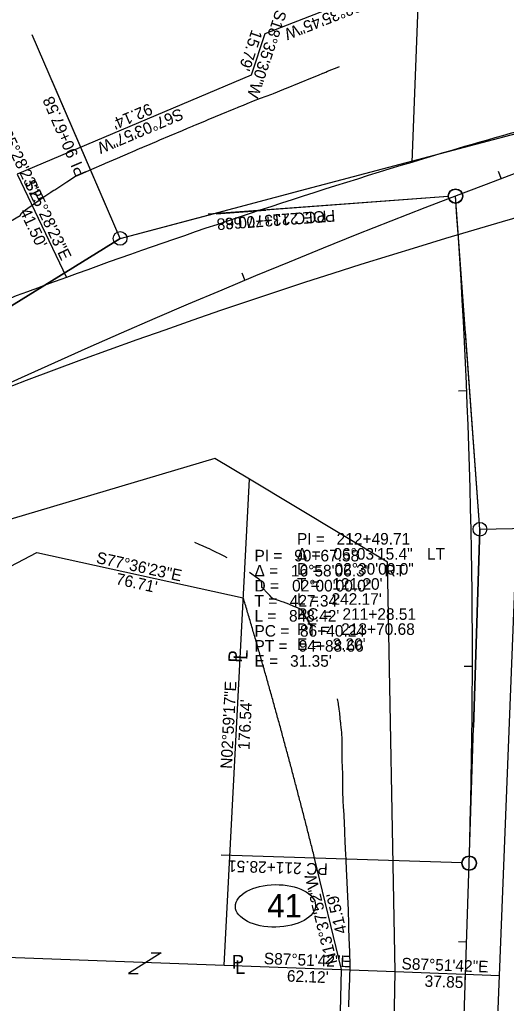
# Model space of a CAD drawing. Extents: x 1145508 to 2262867, y -3126236 to 2021677.
# Drawn here: x 1151538.5 to 1151715.1, y 2020154.7 to 2020511.6 of the extents above; entities that cross this region are included whole.
import ezdxf

# ---------------------------------------------------------------- set-up
doc = ezdxf.new("R2010")
doc.units = 0
for name, color, linetype in [('Default', 7, 'Continuous'), ('DSN_DRFT_Guideline-No-Plot', 7, 'Continuous'), ('DSN_RDWY_Alignment', 7, 'Continuous'), ('DSN_RDWY_Alignment Annotation', 7, 'Continuous'), ('DSN_RDWY_Const Limits', 7, 'Continuous'), ('DSN_ROW_Annotation', 7, 'Continuous'), ('DSN_ROW_Esmnt', 7, 'Continuous'), ('DSN_ROW_Line', 7, 'Continuous'), ('DSN_ROW_Line-Annotation', 7, 'Continuous'), ('DSN_ROW_Prop-Line', 7, 'Continuous'), ('DSN_ROW_Prop-Line-Annotation', 7, 'Continuous'), ('E_Const Align', 7, 'Continuous'), ('EX_QSECTION', 7, 'Continuous'), ('EX_ROW', 7, 'Continuous'), ('EX_ROW_ANNOT', 7, 'Continuous'), ('EX_SECTION', 7, 'Continuous')]:
    doc.layers.add(name, color=color, linetype=linetype)

msp = doc.modelspace()

# ---------------------------------------------------------------- linework, layer by layer
at = {"layer": 'Default'}
msp.add_arc((1152351.97, 2018237.09), 2291.83, 105.0994, 122.23857, dxfattribs=at)
msp.add_open_spline([(1151645.52, 2020207.35), (1151645.13, 2020208.94), (1151644.33, 2020212.12), (1151643.12, 2020216.89), (1151641.91, 2020221.65), (1151640.68, 2020226.41), (1151639.44, 2020231.16), (1151638.2, 2020235.91), (1151636.94, 2020240.65), (1151635.67, 2020245.39), (1151634.39, 2020250.12), (1151633.11, 2020254.84), (1151631.81, 2020259.56), (1151630.5, 2020264.28), (1151629.19, 2020268.99), (1151627.86, 2020273.69), (1151626.52, 2020278.38), (1151625.17, 2020283.08), (1151623.82, 2020287.76), (1151622.45, 2020292.44), (1151621.07, 2020297.11), (1151620.15, 2020300.23), (1151619.68, 2020301.78)], degree=3, dxfattribs=at)
at = {"layer": 'DSN_DRFT_Guideline-No-Plot'}
msp.add_line((1151683.89, 2020538.97), (1151680.79, 2020459.79), dxfattribs=at)
at = {"layer": 'DSN_RDWY_Alignment'}
for p, q in [((1151636.3, 2020448.46), (1151988, 2020541.79)), ((1151705.52, 2020326.67), (1151696.64, 2020447.54)), ((1151574.96, 2020432.19), (1151612.83, 2020442.24)), ((1151211.88, 2020206.81), (1151574.96, 2020432.19)), ((1151701.6, 2020205.53), (1151705.52, 2020326.67))]:
    msp.add_line(p, q, dxfattribs=at)
for points in [[(1151574.96, 2020432.19), (1151543.07, 2020506.09)], [(1151574.96, 2020432.19), (1151550.19, 2020489.57)]]:
    msp.add_lwpolyline(points, dxfattribs=at)
for centre in [(1151696.64, 2020447.54), (1151574.96, 2020432.19), (1151705.52, 2020326.67), (1151701.6, 2020205.53)]:
    msp.add_circle(centre, 2.5, dxfattribs=at)
at = {"layer": 'DSN_RDWY_Alignment Annotation'}
for p, q in [((1151574.96, 2020432.19), (1151551.18, 2020487.28)), ((1151551.18, 2020487.28), (1151551.18, 2020487.28)), ((1151712.14, 2020456.64), (1151713.2, 2020453.84)), ((1151574.96, 2020432.19), (1151644.55, 2020450.65)), ((1151693.97, 2020447.35), (1151606.88, 2020440.95)), ((1151693.97, 2020447.35), (1151609.87, 2020441.17)), ((1151696.64, 2020447.54), (1151696.64, 2020447.54)), ((1151606.88, 2020440.95), (1151606.88, 2020440.95)), ((1151609.87, 2020441.17), (1151627.82, 2020442.49)), ((1151574.96, 2020432.19), (1151513.79, 2020394.22)), ((1151619.09, 2020419.74), (1151620.25, 2020416.97)), ((1151705.52, 2020326.67), (1151700.24, 2020398.47)), ((1151697.73, 2020376.85), (1151700.73, 2020376.98)), ((1151705.52, 2020326.67), (1151703.19, 2020254.71)), ((1151705.52, 2020326.67), (1151765.5, 2020327.9)), ((1151699.79, 2020277.01), (1151702.79, 2020277.01)), ((1151698.93, 2020205.62), (1151611.64, 2020208.44)), ((1151611.64, 2020208.44), (1151611.64, 2020208.44)), ((1151701.6, 2020205.53), (1151701.6, 2020205.53)), ((1151697.68, 2020177.14), (1151700.68, 2020177.04))]:
    msp.add_line(p, q, dxfattribs=at)
for centre in [(1151696.64, 2020447.54), (1151701.6, 2020205.53)]:
    msp.add_circle(centre, 2.67, dxfattribs=at)
at = {"layer": 'DSN_RDWY_Const Limits'}
for points in [[(1151535.19, 2020438.49), (1151538.68, 2020440.53), (1151539.19, 2020441.33), (1151540.69, 2020442.53), (1151541.56, 2020443.13), (1151542.72, 2020443.99), (1151542.8, 2020444.04), (1151542.96, 2020444.17), (1151543.54, 2020444.59), (1151545.56, 2020446.08), (1151546.93, 2020447.09), (1151549.83, 2020448.95), (1151550.37, 2020449.29), (1151550.93, 2020449.65), (1151551.28, 2020449.87), (1151555.59, 2020452.73), (1151559.13, 2020455.04), (1151560.01, 2020455.37), (1151562.1, 2020456.2), (1151562.5, 2020456.37), (1151562.82, 2020456.51), (1151564.72, 2020457.33), (1151569.24, 2020459.27), (1151569.41, 2020459.34), (1151569.63, 2020459.44), (1151574.09, 2020461.37), (1151578.78, 2020463.39), (1151579.3, 2020463.61), (1151582.26, 2020464.88), (1151582.56, 2020465.01), (1151582.69, 2020465.07), (1151583.47, 2020465.4), (1151584.44, 2020465.81), (1151588.16, 2020467.4), (1151589.38, 2020467.92), (1151592.86, 2020469.39), (1151597.56, 2020471.38), (1151599.48, 2020472.19), (1151601.2, 2020472.91), (1151601.5, 2020473.03), (1151601.71, 2020473.12), (1151602.27, 2020473.36), (1151605.69, 2020474.79), (1151606.97, 2020475.33), (1151609.59, 2020476.41), (1151611.69, 2020477.29), (1151616.4, 2020479.24), (1151617.62, 2020479.74), (1151617.86, 2020479.84), (1151618.03, 2020479.91), (1151619.72, 2020480.6), (1151621.12, 2020481.18), (1151623.41, 2020482.12), (1151625.88, 2020483.03), (1151629.96, 2020484.5), (1151630.67, 2020484.79), (1151634.37, 2020486.32), (1151634.64, 2020486.43), (1151635.39, 2020486.74), (1151640.1, 2020488.68), (1151640.1, 2020488.68), (1151644.83, 2020490.62), (1151646.89, 2020491.46), (1151648.58, 2020492.15), (1151648.68, 2020492.19), (1151649.55, 2020492.55), (1151650.24, 2020492.83), (1151654.28, 2020494.47), (1151654.6, 2020494.6)], [(1151613.86, 2020316.3), (1151612.75, 2020316.87), (1151611.24, 2020317.63), (1151609.72, 2020318.36), (1151608.21, 2020319.11), (1151607.36, 2020319.53), (1151606.7, 2020319.84), (1151606.46, 2020319.95), (1151605.15, 2020320.51), (1151603.62, 2020321.19), (1151602.07, 2020321.84)], [(1151644.29, 2020291.58), (1151644.06, 2020291.99), (1151643.14, 2020293.54), (1151643.1, 2020293.61), (1151642.63, 2020294.37), (1151642.19, 2020295.06), (1151641.21, 2020296.57), (1151640.49, 2020297.64), (1151639.95, 2020297.88), (1151639.79, 2020297.95), (1151639.34, 2020298.15), (1151638.05, 2020298.69), (1151636.15, 2020299.46), (1151634.26, 2020300.18), (1151633.77, 2020300.36), (1151632.39, 2020300.85), (1151630.52, 2020301.48), (1151630.12, 2020301.61), (1151629.25, 2020302.59), (1151628.56, 2020303.33), (1151628.51, 2020303.39), (1151628.51, 2020303.39), (1151628.11, 2020303.82), (1151626.94, 2020305.03), (1151626.45, 2020305.53), (1151626.41, 2020306.9), (1151626.3, 2020307.73), (1151625.48, 2020308.4), (1151625.27, 2020308.57), (1151624.11, 2020309.43), (1151622.72, 2020310.42), (1151621.87, 2020311.01)], [(1151658.01, 2020153.41), (1151658.13, 2020158.4), (1151658.13, 2020158.4), (1151658.27, 2020163.4), (1151658.38, 2020168.4), (1151658.27, 2020173.41), (1151658.04, 2020178.42), (1151657.98, 2020181.93), (1151657.97, 2020182.82), (1151657.96, 2020183.42), (1151657.87, 2020188.43), (1151657.61, 2020193.44), (1151657.29, 2020198.45), (1151657.08, 2020203.46), (1151656.96, 2020206.48), (1151656.94, 2020206.98), (1151656.93, 2020207.27), (1151656.88, 2020208.44), (1151656.68, 2020213.35), (1151656.56, 2020216.49), (1151656.48, 2020218.26), (1151656.44, 2020219.07), (1151656.41, 2020219.72), (1151656.22, 2020223.17), (1151656.07, 2020226), (1151655.95, 2020228.08), (1151655.82, 2020231.63), (1151655.81, 2020232.18), (1151655.81, 2020232.98), (1151655.8, 2020235.5), (1151655.77, 2020237.88), (1151655.51, 2020242.78), (1151655.54, 2020244.18), (1151655.54, 2020244.61), (1151655.55, 2020244.94), (1151655.55, 2020244.99), (1151655.58, 2020247.42), (1151655.58, 2020247.43), (1151655.58, 2020247.43), (1151655.59, 2020247.66), (1151655.58, 2020249.22), (1151655.51, 2020251.01), (1151655.43, 2020252.25), (1151655.39, 2020252.79), (1151655.28, 2020254.03), (1151655.23, 2020254.57), (1151655.07, 2020256.11), (1151655.04, 2020256.35), (1151655.03, 2020256.42), (1151654.98, 2020256.82), (1151654.85, 2020258.12), (1151654.66, 2020259.9), (1151654.47, 2020261.41), (1151654.43, 2020261.67), (1151654.26, 2020262.91), (1151654.17, 2020263.44), (1151653.88, 2020265.2)]]:
    msp.add_lwpolyline(points, dxfattribs=at)
at = {"layer": 'DSN_ROW_Esmnt'}
for p, q in [((1151655.32, 2020166.93), (1151645.52, 2020207.35)), ((1151649.76, 2019948.86), (1151655.32, 2020166.93))]:
    msp.add_line(p, q, dxfattribs=at)
msp.add_open_spline([(1151645.52, 2020207.35), (1151645.13, 2020208.94), (1151644.33, 2020212.12), (1151643.12, 2020216.89), (1151641.91, 2020221.65), (1151640.68, 2020226.41), (1151639.44, 2020231.16), (1151638.2, 2020235.91), (1151636.94, 2020240.65), (1151635.67, 2020245.39), (1151634.39, 2020250.12), (1151633.11, 2020254.84), (1151631.81, 2020259.56), (1151630.5, 2020264.28), (1151629.19, 2020268.99), (1151627.86, 2020273.69), (1151626.52, 2020278.38), (1151625.17, 2020283.08), (1151623.82, 2020287.76), (1151622.45, 2020292.44), (1151621.07, 2020297.11), (1151620.15, 2020300.23), (1151619.68, 2020301.78)], degree=3, dxfattribs=at)
at = {"layer": 'DSN_ROW_Line'}
for p, q in [((1151668.67, 2020522.5), (1151627.52, 2020506.37)), ((1151627.52, 2020506.37), (1151622.49, 2020491.4)), ((1151622.49, 2020491.4), (1151537.63, 2020455.5)), ((1151282.65, 2020180.85), (1151544.76, 2020318.25)), ((1151544.76, 2020318.25), (1151619.68, 2020301.78))]:
    msp.add_line(p, q, dxfattribs=at)
at = {"layer": 'DSN_ROW_Line-Annotation'}
msp.add_ellipse((1151631.34, 2020190.02), major_axis=(14.54, 0.23), ratio=0.529773, dxfattribs=at)
at = {"layer": 'DSN_ROW_Prop-Line'}
for p, q in [((1151686.68, 2020609.91), (1151680.79, 2020459.79)), ((1151537.63, 2020455.5), (1151555.48, 2020418.03)), ((1151612.73, 2020168.52), (1151621.93, 2020344.82))]:
    msp.add_line(p, q, dxfattribs=at)
at = {"layer": 'DSN_ROW_Prop-Line-Annotation'}
for p, q in [((1151589.84, 2020172.94), (1151577.99, 2020165.55)), ((1151586.3, 2020172.94), (1151589.84, 2020172.94)), ((1151577.99, 2020165.55), (1151581.54, 2020165.55))]:
    msp.add_line(p, q, dxfattribs=at)
at = {"layer": 'E_Const Align'}
msp.add_line((1151693.25, 2019947.42), (1151701.6, 2020205.53), dxfattribs=at)
for centre, radius, start, end in [((1152722.75, 2017772.83), 2864.79, 104.86102, 121.82944), ((1152722.75, 2017772.83), 2864.79, 104.86102, 121.82944), ((1149410.96, 2020279.63), 2291.83, 358.14731, 4.20159), ((1149410.96, 2020279.63), 2291.83, 358.14731, 4.20159)]:
    msp.add_arc(centre, radius, start, end, dxfattribs=at)
at = {"layer": 'EX_QSECTION'}
for p, q in [((1151292.92, 2020180.46), (1151612.73, 2020168.52)), ((1151612.73, 2020168.52), (1151674.8, 2020166.2)), ((1151674.8, 2020166.2), (1151712.63, 2020164.79))]:
    msp.add_line(p, q, dxfattribs=at)
at = {"layer": 'EX_ROW'}
for p, q in [((1151609.36, 2020352.37), (1151407.12, 2020292.12)), ((1151621.93, 2020344.82), (1151609.36, 2020352.37)), ((1151671.98, 2020314.75), (1151621.93, 2020344.82)), ((1151674.8, 2020166.2), (1151671.98, 2020314.75)), ((1151666.04, 2019745.81), (1151674.8, 2020166.2))]:
    msp.add_line(p, q, dxfattribs=at)
for start, end in [(105.67369, 106.8026), (106.8026, 110.06234), (110.06234, 111.76342)]:
    msp.add_arc((1152351.97, 2018237.09), 2321.83, start, end, dxfattribs=at)
at = {"layer": 'EX_SECTION'}
for p, q in [((1151712.63, 2020164.79), (1151764.37, 2021482.95)), ((1151660.65, 2018840.69), (1151712.63, 2020164.79))]:
    msp.add_line(p, q, dxfattribs=at)

# ---------------------------------------------------------------- texts
at = {"layer": 'DSN_DRFT_Guideline-No-Plot'}
for rotation, p in [(46.4063, (1151627.53, 2020506.31)), (47.1713, (1151622.5, 2020491.34))]:
    msp.add_text('+', height=0.1, rotation=rotation, dxfattribs=at).set_placement(p)
at = {"layer": 'DSN_RDWY_Alignment Annotation'}
for s, rotation, p in [('90+67.58', 113.3452, (1151559.91, 2020462.51)), ('PI ', 113.3452, (1151562.85, 2020455.71)), ('213+70.68', 184.2016, (1151636.54, 2020441.32)), ('213+70.68', 184.2016, (1151639.53, 2020441.54)), ('PCC', 184.2016, (1151649.75, 2020442.29)), ('POE ', 184.2016, (1151652.85, 2020442.52)), ('211+28.51', 178.1473, (1151640.88, 2020205.7)), ('PC', 178.1473, (1151650.39, 2020205.39))]:
    msp.add_text(s, height=4.2, rotation=rotation, dxfattribs=at).set_placement(p)
for s, p in [('PI = ', (1151639.13, 2020321.11)), ('212+49.71', (1151653.53, 2020321.11)), ('PI = ', (1151623.72, 2020315.01)), ('90+67.58', (1151638.13, 2020315.01)), ('Δ = ', (1151639.13, 2020315.65)), ('06°03\'15.4"', (1151652.36, 2020315.65)), (' LT', (1151684.72, 2020315.65)), ('Δ = ', (1151623.72, 2020309.55)), ('16°58\'06.3"', (1151636.96, 2020309.55)), ('D = ', (1151639.13, 2020310.19)), ('02°30\'00.0"', (1151652.77, 2020310.19)), (' RT', (1151669.31, 2020309.55)), ('D = ', (1151623.72, 2020304.09)), ('02°00\'00.0"', (1151637.36, 2020304.09)), ('T = ', (1151639.13, 2020304.73)), ("121.20'", (1151651.94, 2020304.73)), ('T = ', (1151623.72, 2020298.63)), ("427.34'", (1151636.53, 2020298.63)), ('L = ', (1151639.13, 2020299.27)), ("242.17'", (1151651.66, 2020299.27)), ('L = ', (1151623.72, 2020293.17)), ("848.42'", (1151636.25, 2020293.17)), ('PC = ', (1151639.13, 2020293.81)), ('211+28.51', (1151655.63, 2020293.81)), ('PC = ', (1151623.72, 2020287.71)), ('PT = ', (1151639.13, 2020288.35)), ('86+40.24', (1151640.23, 2020287.71)), ('213+70.68', (1151655.18, 2020288.35)), ('PT = ', (1151623.72, 2020282.25)), ('E = ', (1151639.13, 2020282.89)), ('94+88.66', (1151639.77, 2020282.25)), ("3.20'", (1151652.05, 2020282.89)), ('E = ', (1151623.72, 2020276.79)), ("31.35'", (1151636.64, 2020276.79))]:
    msp.add_text(s, height=4.2, dxfattribs=at).set_placement(p)
at = {"layer": 'DSN_ROW_Annotation'}
for s, rotation, p in [('S68°35\'45"W', 201.4042, (1151664.97, 2020520.08)), ('S18°35\'30"W', 251.4084, (1151631.52, 2020515.44)), ("15.79'", 251.4084, (1151622.77, 2020508.24)), ('S67°03\'57"W', 202.9343, (1151596.77, 2020479.55)), ("92.14'", 202.9343, (1151585.58, 2020481.33)), ('S25°28\'23"E', 295.4731, (1151529.95, 2020473.73)), ('S25°28\'23"E', 295.4731, (1151540.16, 2020452.29)), ("41.50'", 295.4731, (1151538.45, 2020441.93)), ('S77°36\'23"E', 347.6063, (1151566.04, 2020314.49)), ("76.71'", 347.6063, (1151573.16, 2020306.78)), ('N02°59\'17"E', 87.012, (1151615.54, 2020239.68)), ("176.54'", 87.012, (1151621.91, 2020246.56)), ('N13°37\'52"W', 103.6311, (1151653.81, 2020169.37)), ("41.59'", 103.6311, (1151657.3, 2020180.42))]:
    msp.add_text(s, height=4.2, rotation=rotation, dxfattribs=at).set_placement(p)
at = {"layer": 'DSN_ROW_Line-Annotation'}
msp.add_text('41', height=8.5, dxfattribs=at).set_placement((1151628.33, 2020185.81))
at = {"layer": 'DSN_ROW_Prop-Line-Annotation'}
for s, p in [('L', (1151621.13, 2020279.21)), ('P', (1151619.16, 2020278.15))]:
    msp.add_text(s, height=5, rotation=87.03, dxfattribs=at).set_placement(p)
for s, p in [('P', (1151615.49, 2020167.23)), ('L', (1151616.66, 2020165.31))]:
    msp.add_text(s, height=5, dxfattribs=at).set_placement(p)
at = {"layer": 'EX_ROW_ANNOT'}
for s, p in [('S87°51\'42"E', (1151627.05, 2020168.89)), ('S87°51\'42"E', (1151627.05, 2020168.89)), ('S87°51\'42"E', (1151677, 2020167.02)), ('S87°51\'42"E', (1151677, 2020167.02)), ("62.12'", (1151635.43, 2020162.57)), ("62.12'", (1151635.43, 2020162.57)), ("37.85'", (1151685.38, 2020160.7)), ("37.85'", (1151685.38, 2020160.7))]:
    msp.add_text(s, height=4.2, rotation=357.8615, dxfattribs=at).set_placement(p)

doc.saveas('drawing.dxf')
